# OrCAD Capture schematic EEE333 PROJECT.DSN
size A
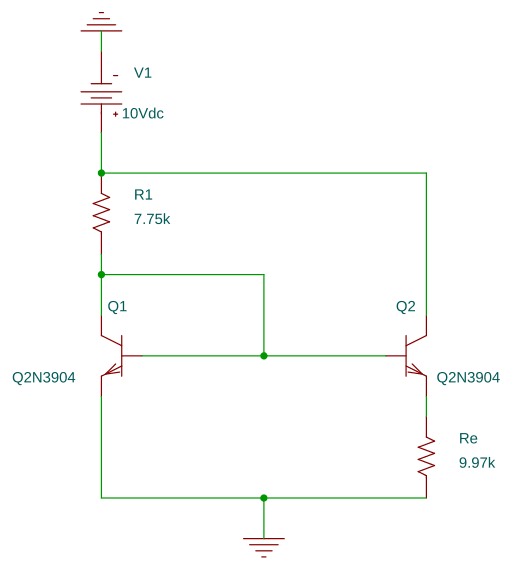
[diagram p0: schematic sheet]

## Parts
Q1  Q2N3904  [TO92]
Q2  Q2N3904  [TO92]
R1  7.75k  [AX/RC05]
Re  9.97k  [AX/RC05]
V1  VDC

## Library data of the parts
Q1 Q2 = Q2N3904
R1 Re = R
V1 = VDC: DC: 10Vdc

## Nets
0: Q1.1(e) Re.1 V1.1(-)
N00123: Q2.3(c) R1.2 V1.0(+)
N00144: Q1.2(b) Q1.3(c) Q2.2(b) R1.1
N00365: Q2.1(e) Re.2
